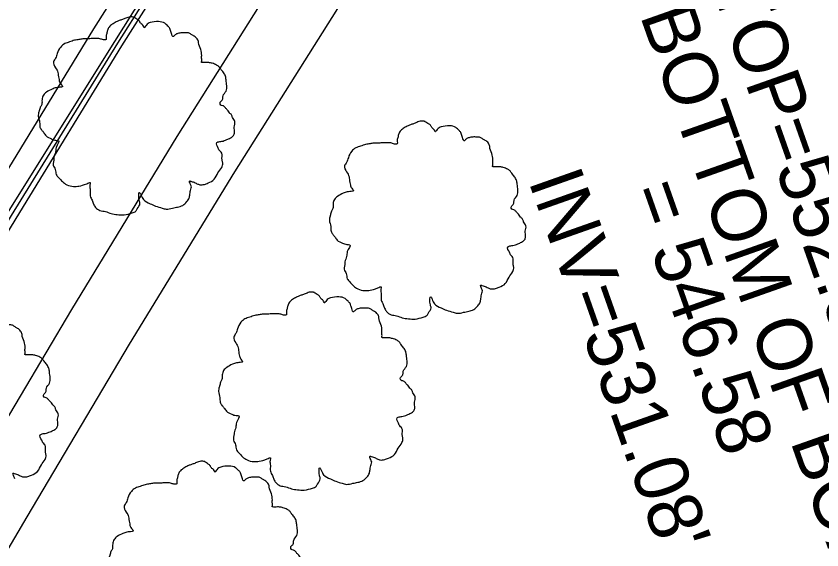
# Model space of a CAD drawing. Extents: x 2004847 to 2009016, y 1134161 to 1140101.
# Drawn here: x 2007935.1 to 2007994.5, y 1139061.5 to 1139100.8 of the extents above; entities that cross this region are included whole.
import ezdxf

# ---------------------------------------------------------------- set-up
doc = ezdxf.new("R2010")
doc.units = 0
for name, color, linetype in [('RD_EX_Conc', 7, 'Continuous'), ('RD_EX_Curb', 7, 'Continuous'), ('RD_EX_DR_Inlet_txCode', 7, 'Continuous'), ('RD_EX_Road', 7, 'Continuous'), ('RD_EX_VEG', 7, 'Continuous')]:
    doc.layers.add(name, color=color, linetype=linetype)

msp = doc.modelspace()

# ---------------------------------------------------------------- linework, layer by layer
at = {"layer": 'RD_EX_Conc'}
for points in [[(2008012.258, 1139192.316), (2008003.651, 1139179.799), (2007995.336, 1139167.43), (2007987.157, 1139154.821), (2007979.201, 1139142.322), (2007971.095, 1139129.729), (2007962.904, 1139117.197), (2007954.856, 1139104.534), (2007946.938, 1139091.958), (2007939.166, 1139079.213), (2007931.58, 1139066.441), (2007923.915, 1139053.39), (2007916.339, 1139040.676), (2007908.934, 1139027.568), (2007901.347, 1139014.745), (2007894.028, 1139001.836), (2007886.768, 1138988.672), (2007879.687, 1138975.615), (2007872.659, 1138962.368), (2007865.778, 1138949.249), (2007860.038, 1138937.972)], [(2008016.296, 1139189.467), (2008007.766, 1139177.029), (2007999.476, 1139164.697), (2007991.297, 1139152.062), (2007983.392, 1139139.642), (2007975.292, 1139127.057), (2007967.109, 1139114.537), (2007959.059, 1139101.871), (2007951.178, 1139089.355), (2007943.426, 1139076.643), (2007935.879, 1139063.936), (2007928.171, 1139050.827), (2007920.647, 1139038.202), (2007913.233, 1139025.065), (2007905.673, 1139012.288), (2007898.395, 1138999.453), (2007891.121, 1138986.277), (2007884.076, 1138973.288), (2007877.05, 1138960.043), (2007870.213, 1138947.011), (2007864.473, 1138935.734)]]:
    msp.add_lwpolyline(points, dxfattribs=at)
at = {"layer": 'RD_EX_Curb'}
for points in [[(2007989.294, 1139171.584), (2007981.119, 1139159.117), (2007979.485, 1139156.609), (2007974.548, 1139148.778), (2007966.518, 1139136.415), (2007958.375, 1139123.821), (2007950.518, 1139111.44), (2007942.559, 1139098.831), (2007934.71, 1139086.14), (2007927.171, 1139073.615), (2007919.542, 1139060.701), (2007912.08, 1139047.949), (2007907.108, 1139039.406), (2007903.841, 1139033.792), (2007897.425, 1139022.77), (2007893.765, 1139016.325), (2007888.06, 1139006.217), (2007880.903, 1138993.098), (2007873.794, 1138980.156), (2007868.217, 1138969.601), (2007863.906, 1138961.461), (2007859.666, 1138953.372), (2007853.475, 1138941.292)], [(2007989.587, 1139171.391), (2007981.43, 1139158.913), (2007979.864, 1139156.364), (2007974.922, 1139148.536), (2007966.859, 1139136.199), (2007958.73, 1139123.596), (2007950.844, 1139111.24), (2007942.864, 1139098.646), (2007935.074, 1139085.921), (2007927.484, 1139073.434), (2007919.887, 1139060.501), (2007912.354, 1139047.794), (2007907.427, 1139039.225), (2007904.224, 1139033.576), (2007897.811, 1139022.558), (2007894.152, 1139016.114), (2007888.449, 1139006.01), (2007881.293, 1138992.892), (2007874.167, 1138979.964), (2007868.571, 1138969.419), (2007864.285, 1138961.268), (2007860.13, 1138953.14), (2007853.85, 1138941.104)], [(2007974.293, 1139148.944), (2007973.079, 1139147.086), (2007966.226, 1139136.6), (2007958.109, 1139123.989), (2007950.254, 1139111.602), (2007942.331, 1139098.97), (2007934.431, 1139086.308), (2007926.899, 1139073.773), (2007919.27, 1139060.859), (2007911.797, 1139048.109), (2007906.875, 1139039.537), (2007903.644, 1139033.903)]]:
    msp.add_lwpolyline(points, dxfattribs=at)
at = {"layer": 'RD_EX_Road'}
msp.add_lwpolyline([(2007987.563, 1139172.722), (2007979.344, 1139160.275), (2007977.681, 1139157.78), (2007972.648, 1139150.012), (2007964.693, 1139137.571), (2007956.638, 1139124.92), (2007948.783, 1139112.504), (2007940.798, 1139099.901), (2007932.989, 1139087.177), (2007925.419, 1139074.63), (2007917.868, 1139061.671), (2007910.231, 1139048.995), (2007905.309, 1139040.422), (2007902.074, 1139034.791), (2007895.646, 1139023.748), (2007891.982, 1139017.295), (2007886.268, 1139007.171), (2007879.109, 1138994.048), (2007871.98, 1138981.089), (2007866.389, 1138970.541), (2007862.074, 1138962.393), (2007857.734, 1138954.34), (2007851.618, 1138942.222)], dxfattribs=at)
at = {"layer": 'RD_EX_VEG'}
for points in [[(2007943.793, 1139100.752), (2007943.493, 1139100.777), (2007943.168, 1139100.677), (2007942.918, 1139100.578), (2007942.693, 1139100.503), (2007942.468, 1139100.403), (2007942.168, 1139100.228), (2007941.943, 1139100.028), (2007941.818, 1139099.778), (2007941.768, 1139099.553), (2007941.718, 1139099.278), (2007941.718, 1139099.103), (2007941.594, 1139099.078), (2007941.444, 1139099.103), (2007941.194, 1139099.178), (2007940.944, 1139099.178), (2007940.694, 1139099.178), (2007940.344, 1139099.153), (2007939.994, 1139099.153), (2007939.719, 1139099.103), (2007939.394, 1139099.053), (2007939.02, 1139098.928), (2007938.67, 1139098.803), (2007938.37, 1139098.553), (2007938.12, 1139098.079), (2007937.995, 1139097.729), (2007937.845, 1139097.479), (2007937.995, 1139097.029), (2007938.17, 1139096.679), (2007938.195, 1139096.479), (2007938.27, 1139096.055), (2007938.37, 1139095.83), (2007938.495, 1139095.63), (2007938.42, 1139095.605), (2007938.045, 1139095.555), (2007937.745, 1139095.455), (2007937.32, 1139095.23), (2007937.095, 1139095.005), (2007936.995, 1139094.68), (2007936.971, 1139094.33), (2007936.871, 1139094.13), (2007936.796, 1139093.855), (2007936.771, 1139093.78), (2007936.721, 1139093.456), (2007936.821, 1139093.006), (2007936.846, 1139092.656), (2007936.971, 1139092.431), (2007937.12, 1139092.256), (2007937.295, 1139092.006), (2007937.695, 1139091.781), (2007938.02, 1139091.681), (2007938.22, 1139091.656), (2007938.045, 1139091.157), (2007937.995, 1139090.807), (2007937.87, 1139090.407), (2007937.87, 1139090.332), (2007937.82, 1139089.857), (2007937.97, 1139089.532), (2007938.045, 1139089.158), (2007938.22, 1139088.933), (2007938.495, 1139088.633), (2007938.82, 1139088.408), (2007939.32, 1139088.283), (2007939.719, 1139088.308), (2007940.294, 1139088.483), (2007940.544, 1139088.558), (2007940.519, 1139088.383), (2007940.544, 1139088.008), (2007940.544, 1139087.583), (2007940.694, 1139087.258), (2007940.794, 1139086.983), (2007940.944, 1139086.734), (2007941.269, 1139086.509), (2007941.668, 1139086.434), (2007942.093, 1139086.284), (2007942.543, 1139086.209), (2007943.043, 1139086.184), (2007943.643, 1139086.334), (2007943.917, 1139086.459), (2007944.017, 1139086.634), (2007944.217, 1139087.008), (2007944.167, 1139087.233), (2007944.192, 1139087.833), (2007944.292, 1139087.658), (2007944.467, 1139087.308), (2007944.967, 1139087.008), (2007945.367, 1139086.834), (2007945.842, 1139086.684), (2007946.142, 1139086.609), (2007946.616, 1139086.684), (2007946.991, 1139086.759), (2007947.366, 1139086.884), (2007947.666, 1139087.158), (2007947.841, 1139087.433), (2007947.891, 1139087.708), (2007947.966, 1139088.083), (2007948.016, 1139088.258)], [(2007948.016, 1139088.258), (2007947.941, 1139088.433), (2007947.891, 1139088.683), (2007947.966, 1139088.658), (2007948.141, 1139088.608), (2007948.416, 1139088.483), (2007948.64, 1139088.408), (2007948.965, 1139088.433), (2007949.24, 1139088.533), (2007949.69, 1139088.808), (2007949.965, 1139089.282), (2007950.24, 1139089.682), (2007950.315, 1139090.007), (2007950.265, 1139090.232), (2007950.24, 1139090.732), (2007950.04, 1139090.982), (2007949.99, 1139091.107), (2007949.89, 1139091.506), (2007949.965, 1139091.556), (2007950.24, 1139091.606), (2007950.615, 1139091.731), (2007950.889, 1139091.856), (2007951.114, 1139092.031), (2007951.189, 1139092.256), (2007951.164, 1139092.656), (2007951.214, 1139093.056), (2007951.139, 1139093.206), (2007951.039, 1139093.356), (2007950.964, 1139093.556), (2007950.814, 1139093.705), (2007950.715, 1139093.855), (2007950.615, 1139093.955), (2007950.49, 1139094.105), (2007950.315, 1139094.23), (2007950.165, 1139094.28), (2007950.115, 1139094.43), (2007950.265, 1139094.63), (2007950.315, 1139094.73), (2007950.34, 1139094.955), (2007950.565, 1139095.305), (2007950.615, 1139095.705), (2007950.565, 1139096.129), (2007950.515, 1139096.404), (2007950.365, 1139096.679), (2007950.165, 1139096.929), (2007950.04, 1139097.104), (2007949.865, 1139097.229), (2007949.54, 1139097.354), (2007949.29, 1139097.404), (2007948.94, 1139097.404), (2007948.74, 1139097.454), (2007948.765, 1139097.504), (2007948.765, 1139097.654), (2007948.765, 1139097.929), (2007948.69, 1139098.378), (2007948.54, 1139098.878), (2007948.54, 1139098.903), (2007948.44, 1139099.153), (2007948.216, 1139099.353), (2007948.041, 1139099.453), (2007947.841, 1139099.578), (2007947.591, 1139099.603), (2007947.291, 1139099.603), (2007947.016, 1139099.553), (2007946.816, 1139099.453), (2007946.641, 1139099.328), (2007946.566, 1139099.478), (2007946.466, 1139099.778), (2007946.416, 1139099.928), (2007946.266, 1139100.103), (2007946.042, 1139100.303), (2007945.592, 1139100.428), (2007944.967, 1139100.353), (2007944.667, 1139100.153), (2007944.517, 1139099.978), (2007944.467, 1139100.103), (2007944.267, 1139100.303), (2007944.167, 1139100.478), (2007943.992, 1139100.603), (2007943.843, 1139100.702), (2007943.743, 1139100.752)], [(2007965.248, 1139093.071), (2007964.948, 1139093.096), (2007964.623, 1139092.996), (2007964.373, 1139092.896), (2007964.148, 1139092.821), (2007963.923, 1139092.721), (2007963.623, 1139092.546), (2007963.398, 1139092.346), (2007963.273, 1139092.097), (2007963.223, 1139091.872), (2007963.173, 1139091.597), (2007963.173, 1139091.422), (2007963.049, 1139091.397), (2007962.899, 1139091.422), (2007962.649, 1139091.497), (2007962.399, 1139091.497), (2007962.149, 1139091.497), (2007961.799, 1139091.472), (2007961.449, 1139091.472), (2007961.174, 1139091.422), (2007960.849, 1139091.372), (2007960.475, 1139091.247), (2007960.125, 1139091.122), (2007959.825, 1139090.872), (2007959.575, 1139090.397), (2007959.45, 1139090.047), (2007959.3, 1139089.798), (2007959.45, 1139089.348), (2007959.625, 1139088.998), (2007959.65, 1139088.798), (2007959.725, 1139088.373), (2007959.825, 1139088.148), (2007959.95, 1139087.948), (2007959.875, 1139087.923), (2007959.5, 1139087.873), (2007959.2, 1139087.773), (2007958.775, 1139087.549), (2007958.55, 1139087.324), (2007958.45, 1139086.999), (2007958.426, 1139086.649), (2007958.326, 1139086.449), (2007958.251, 1139086.174), (2007958.226, 1139086.099), (2007958.176, 1139085.774), (2007958.276, 1139085.324), (2007958.301, 1139084.975), (2007958.426, 1139084.75), (2007958.575, 1139084.575), (2007958.75, 1139084.325), (2007959.15, 1139084.1), (2007959.475, 1139084), (2007959.675, 1139083.975), (2007959.5, 1139083.475), (2007959.45, 1139083.125), (2007959.325, 1139082.726), (2007959.325, 1139082.651), (2007959.275, 1139082.176), (2007959.425, 1139081.851), (2007959.5, 1139081.476), (2007959.675, 1139081.251), (2007959.95, 1139080.951), (2007960.275, 1139080.727), (2007960.775, 1139080.602), (2007961.174, 1139080.627), (2007961.749, 1139080.801), (2007961.999, 1139080.876), (2007961.974, 1139080.702), (2007961.999, 1139080.327), (2007961.999, 1139079.902), (2007962.149, 1139079.577), (2007962.249, 1139079.302), (2007962.399, 1139079.052), (2007962.724, 1139078.827), (2007963.123, 1139078.752), (2007963.548, 1139078.602), (2007963.998, 1139078.527), (2007964.498, 1139078.502), (2007965.098, 1139078.652), (2007965.372, 1139078.777), (2007965.472, 1139078.952), (2007965.672, 1139079.327), (2007965.622, 1139079.552), (2007965.647, 1139080.152), (2007965.747, 1139079.977), (2007965.922, 1139079.627), (2007966.422, 1139079.327), (2007966.822, 1139079.152), (2007967.297, 1139079.002), (2007967.597, 1139078.927), (2007968.071, 1139079.002), (2007968.446, 1139079.077), (2007968.821, 1139079.202), (2007969.121, 1139079.477), (2007969.296, 1139079.752), (2007969.346, 1139080.027), (2007969.421, 1139080.402), (2007969.471, 1139080.577)], [(2007969.471, 1139080.577), (2007969.396, 1139080.752), (2007969.346, 1139081.001), (2007969.421, 1139080.976), (2007969.596, 1139080.926), (2007969.871, 1139080.801), (2007970.095, 1139080.727), (2007970.42, 1139080.752), (2007970.695, 1139080.851), (2007971.145, 1139081.126), (2007971.42, 1139081.601), (2007971.695, 1139082.001), (2007971.77, 1139082.326), (2007971.72, 1139082.551), (2007971.695, 1139083.05), (2007971.495, 1139083.3), (2007971.445, 1139083.425), (2007971.345, 1139083.825), (2007971.42, 1139083.875), (2007971.695, 1139083.925), (2007972.07, 1139084.05), (2007972.344, 1139084.175), (2007972.569, 1139084.35), (2007972.644, 1139084.575), (2007972.619, 1139084.975), (2007972.669, 1139085.374), (2007972.594, 1139085.524), (2007972.494, 1139085.674), (2007972.419, 1139085.874), (2007972.269, 1139086.024), (2007972.17, 1139086.174), (2007972.07, 1139086.274), (2007971.945, 1139086.424), (2007971.77, 1139086.549), (2007971.62, 1139086.599), (2007971.57, 1139086.749), (2007971.72, 1139086.949), (2007971.77, 1139087.049), (2007971.795, 1139087.274), (2007972.02, 1139087.623), (2007972.07, 1139088.023), (2007972.02, 1139088.448), (2007971.97, 1139088.723), (2007971.82, 1139088.998), (2007971.62, 1139089.248), (2007971.495, 1139089.423), (2007971.32, 1139089.548), (2007970.995, 1139089.673), (2007970.745, 1139089.723), (2007970.395, 1139089.723), (2007970.195, 1139089.773), (2007970.22, 1139089.823), (2007970.22, 1139089.972), (2007970.22, 1139090.247), (2007970.145, 1139090.697), (2007969.995, 1139091.197), (2007969.995, 1139091.222), (2007969.895, 1139091.472), (2007969.671, 1139091.672), (2007969.496, 1139091.772), (2007969.296, 1139091.897), (2007969.046, 1139091.922), (2007968.746, 1139091.922), (2007968.471, 1139091.872), (2007968.271, 1139091.772), (2007968.096, 1139091.647), (2007968.021, 1139091.797), (2007967.921, 1139092.097), (2007967.871, 1139092.246), (2007967.721, 1139092.421), (2007967.497, 1139092.621), (2007967.047, 1139092.746), (2007966.422, 1139092.671), (2007966.122, 1139092.471), (2007965.972, 1139092.296), (2007965.922, 1139092.421), (2007965.722, 1139092.621), (2007965.622, 1139092.796), (2007965.447, 1139092.921), (2007965.298, 1139093.021), (2007965.198, 1139093.071)], [(2007957.08, 1139080.466), (2007956.78, 1139080.491), (2007956.455, 1139080.391), (2007956.205, 1139080.291), (2007955.98, 1139080.216), (2007955.756, 1139080.116), (2007955.456, 1139079.941), (2007955.231, 1139079.741), (2007955.106, 1139079.491), (2007955.056, 1139079.266), (2007955.006, 1139078.991), (2007955.006, 1139078.816), (2007954.881, 1139078.791), (2007954.731, 1139078.816), (2007954.481, 1139078.891), (2007954.231, 1139078.891), (2007953.981, 1139078.891), (2007953.631, 1139078.866), (2007953.282, 1139078.866), (2007953.007, 1139078.816), (2007952.682, 1139078.766), (2007952.307, 1139078.641), (2007951.957, 1139078.516), (2007951.657, 1139078.266), (2007951.407, 1139077.792), (2007951.282, 1139077.442), (2007951.133, 1139077.192), (2007951.282, 1139076.742), (2007951.457, 1139076.392), (2007951.482, 1139076.192), (2007951.557, 1139075.768), (2007951.657, 1139075.543), (2007951.782, 1139075.343), (2007951.707, 1139075.318), (2007951.332, 1139075.268), (2007951.033, 1139075.168), (2007950.608, 1139074.943), (2007950.383, 1139074.718), (2007950.283, 1139074.393), (2007950.258, 1139074.043), (2007950.158, 1139073.843), (2007950.083, 1139073.569), (2007950.058, 1139073.494), (2007950.008, 1139073.169), (2007950.108, 1139072.719), (2007950.133, 1139072.369), (2007950.258, 1139072.144), (2007950.408, 1139071.969), (2007950.583, 1139071.719), (2007950.983, 1139071.494), (2007951.307, 1139071.394), (2007951.507, 1139071.37), (2007951.332, 1139070.87), (2007951.282, 1139070.52), (2007951.158, 1139070.12), (2007951.158, 1139070.045), (2007951.108, 1139069.57), (2007951.257, 1139069.245), (2007951.332, 1139068.871), (2007951.507, 1139068.646), (2007951.782, 1139068.346), (2007952.107, 1139068.121), (2007952.607, 1139067.996), (2007953.007, 1139068.021), (2007953.582, 1139068.196), (2007953.831, 1139068.271), (2007953.806, 1139068.096), (2007953.831, 1139067.721), (2007953.831, 1139067.296), (2007953.981, 1139066.971), (2007954.081, 1139066.697), (2007954.231, 1139066.447), (2007954.556, 1139066.222), (2007954.956, 1139066.147), (2007955.381, 1139065.997), (2007955.831, 1139065.922), (2007956.33, 1139065.897), (2007956.93, 1139066.047), (2007957.205, 1139066.172), (2007957.305, 1139066.347), (2007957.505, 1139066.722), (2007957.455, 1139066.946), (2007957.48, 1139067.546), (2007957.58, 1139067.371), (2007957.755, 1139067.021), (2007958.254, 1139066.722), (2007958.654, 1139066.547), (2007959.129, 1139066.397), (2007959.429, 1139066.322), (2007959.904, 1139066.397), (2007960.279, 1139066.472), (2007960.653, 1139066.597), (2007960.953, 1139066.871), (2007961.128, 1139067.146), (2007961.178, 1139067.421), (2007961.253, 1139067.796), (2007961.303, 1139067.971)], [(2007961.303, 1139067.971), (2007961.228, 1139068.146), (2007961.178, 1139068.396), (2007961.253, 1139068.371), (2007961.428, 1139068.321), (2007961.703, 1139068.196), (2007961.928, 1139068.121), (2007962.253, 1139068.146), (2007962.528, 1139068.246), (2007962.977, 1139068.521), (2007963.252, 1139068.996), (2007963.527, 1139069.395), (2007963.602, 1139069.72), (2007963.552, 1139069.945), (2007963.527, 1139070.445), (2007963.327, 1139070.695), (2007963.277, 1139070.82), (2007963.177, 1139071.22), (2007963.252, 1139071.27), (2007963.527, 1139071.32), (2007963.902, 1139071.444), (2007964.177, 1139071.569), (2007964.402, 1139071.744), (2007964.477, 1139071.969), (2007964.452, 1139072.369), (2007964.502, 1139072.769), (2007964.427, 1139072.919), (2007964.327, 1139073.069), (2007964.252, 1139073.269), (2007964.102, 1139073.419), (2007964.002, 1139073.569), (2007963.902, 1139073.668), (2007963.777, 1139073.818), (2007963.602, 1139073.943), (2007963.452, 1139073.993), (2007963.402, 1139074.143), (2007963.552, 1139074.343), (2007963.602, 1139074.443), (2007963.627, 1139074.668), (2007963.852, 1139075.018), (2007963.902, 1139075.418), (2007963.852, 1139075.843), (2007963.802, 1139076.117), (2007963.652, 1139076.392), (2007963.452, 1139076.642), (2007963.327, 1139076.817), (2007963.152, 1139076.942), (2007962.827, 1139077.067), (2007962.578, 1139077.117), (2007962.228, 1139077.117), (2007962.028, 1139077.167), (2007962.053, 1139077.217), (2007962.053, 1139077.367), (2007962.053, 1139077.642), (2007961.978, 1139078.092), (2007961.828, 1139078.591), (2007961.828, 1139078.616), (2007961.728, 1139078.866), (2007961.503, 1139079.066), (2007961.328, 1139079.166), (2007961.128, 1139079.291), (2007960.878, 1139079.316), (2007960.578, 1139079.316), (2007960.304, 1139079.266), (2007960.104, 1139079.166), (2007959.929, 1139079.041), (2007959.854, 1139079.191), (2007959.754, 1139079.491), (2007959.704, 1139079.641), (2007959.554, 1139079.816), (2007959.329, 1139080.016), (2007958.879, 1139080.141), (2007958.254, 1139080.066), (2007957.955, 1139079.866), (2007957.805, 1139079.691), (2007957.755, 1139079.816), (2007957.555, 1139080.016), (2007957.455, 1139080.191), (2007957.28, 1139080.316), (2007957.13, 1139080.416), (2007957.03, 1139080.466)], [(2007934.996, 1139066.725), (2007934.921, 1139066.9), (2007934.871, 1139067.15), (2007934.946, 1139067.125), (2007935.12, 1139067.075), (2007935.395, 1139066.95), (2007935.62, 1139066.875), (2007935.945, 1139066.9), (2007936.22, 1139067), (2007936.67, 1139067.275), (2007936.945, 1139067.75), (2007937.22, 1139068.149), (2007937.295, 1139068.474), (2007937.245, 1139068.699), (2007937.22, 1139069.199), (2007937.02, 1139069.449), (2007936.97, 1139069.574), (2007936.87, 1139069.974), (2007936.945, 1139070.024), (2007937.22, 1139070.074), (2007937.594, 1139070.199), (2007937.869, 1139070.323), (2007938.094, 1139070.498), (2007938.169, 1139070.723), (2007938.144, 1139071.123), (2007938.194, 1139071.523), (2007938.119, 1139071.673), (2007938.019, 1139071.823), (2007937.944, 1139072.023), (2007937.794, 1139072.173), (2007937.694, 1139072.323), (2007937.594, 1139072.423), (2007937.469, 1139072.573), (2007937.295, 1139072.697), (2007937.145, 1139072.747), (2007937.095, 1139072.897), (2007937.245, 1139073.097), (2007937.295, 1139073.197), (2007937.319, 1139073.422), (2007937.544, 1139073.772), (2007937.594, 1139074.172), (2007937.544, 1139074.597), (2007937.494, 1139074.872), (2007937.344, 1139075.146), (2007937.145, 1139075.396), (2007937.02, 1139075.571), (2007936.845, 1139075.696), (2007936.52, 1139075.821), (2007936.27, 1139075.871), (2007935.92, 1139075.871), (2007935.72, 1139075.921), (2007935.745, 1139075.971), (2007935.745, 1139076.121), (2007935.745, 1139076.396), (2007935.67, 1139076.846), (2007935.52, 1139077.345), (2007935.52, 1139077.37), (2007935.42, 1139077.62), (2007935.195, 1139077.82), (2007935.021, 1139077.92), (2007934.821, 1139078.045), (2007934.571, 1139078.07), (2007934.271, 1139078.07), (2007933.996, 1139078.02), (2007933.796, 1139077.92), (2007933.621, 1139077.795), (2007933.546, 1139077.945), (2007933.446, 1139078.245), (2007933.396, 1139078.395), (2007933.246, 1139078.57), (2007933.021, 1139078.77), (2007932.572, 1139078.895), (2007931.947, 1139078.82), (2007931.647, 1139078.62), (2007931.497, 1139078.445), (2007931.447, 1139078.57), (2007931.247, 1139078.77), (2007931.147, 1139078.945), (2007930.972, 1139079.07), (2007930.822, 1139079.17), (2007930.722, 1139079.22)], [(2007949.001, 1139067.997), (2007948.701, 1139068.022), (2007948.377, 1139067.922), (2007948.127, 1139067.822), (2007947.902, 1139067.747), (2007947.677, 1139067.647), (2007947.377, 1139067.472), (2007947.152, 1139067.272), (2007947.027, 1139067.023), (2007946.977, 1139066.798), (2007946.927, 1139066.523), (2007946.927, 1139066.348), (2007946.802, 1139066.323), (2007946.652, 1139066.348), (2007946.402, 1139066.423), (2007946.153, 1139066.423), (2007945.903, 1139066.423), (2007945.553, 1139066.398), (2007945.203, 1139066.398), (2007944.928, 1139066.348), (2007944.603, 1139066.298), (2007944.228, 1139066.173), (2007943.879, 1139066.048), (2007943.579, 1139065.798), (2007943.329, 1139065.323), (2007943.204, 1139064.974), (2007943.054, 1139064.724), (2007943.204, 1139064.274), (2007943.379, 1139063.924), (2007943.404, 1139063.724), (2007943.479, 1139063.299), (2007943.579, 1139063.074), (2007943.704, 1139062.874), (2007943.629, 1139062.849), (2007943.254, 1139062.799), (2007942.954, 1139062.7), (2007942.529, 1139062.475), (2007942.304, 1139062.25), (2007942.204, 1139061.925), (2007942.179, 1139061.575), (2007942.079, 1139061.375), (2007942.004, 1139061.1), (2007941.979, 1139061.025), (2007941.929, 1139060.7), (2007942.029, 1139060.251), (2007942.054, 1139059.901), (2007942.179, 1139059.676), (2007942.329, 1139059.501), (2007942.504, 1139059.251), (2007942.904, 1139059.026), (2007943.229, 1139058.926), (2007943.429, 1139058.901), (2007943.254, 1139058.401), (2007943.204, 1139058.052), (2007943.079, 1139057.652), (2007943.079, 1139057.577), (2007943.029, 1139057.102), (2007943.179, 1139056.777), (2007943.254, 1139056.402), (2007943.429, 1139056.177), (2007943.704, 1139055.877), (2007944.028, 1139055.653), (2007944.528, 1139055.528), (2007944.928, 1139055.553), (2007945.503, 1139055.728), (2007945.753, 1139055.803), (2007945.728, 1139055.628), (2007945.753, 1139055.253), (2007945.753, 1139054.828), (2007945.903, 1139054.503), (2007946.003, 1139054.228), (2007946.153, 1139053.978), (2007946.477, 1139053.753), (2007946.877, 1139053.678), (2007947.302, 1139053.529), (2007947.752, 1139053.454), (2007948.252, 1139053.429), (2007948.851, 1139053.578), (2007949.126, 1139053.703), (2007949.226, 1139053.878), (2007949.426, 1139054.253), (2007949.376, 1139054.478), (2007949.401, 1139055.078), (2007949.501, 1139054.903), (2007949.676, 1139054.553), (2007950.176, 1139054.253), (2007950.576, 1139054.078), (2007951.05, 1139053.928), (2007951.35, 1139053.853), (2007951.825, 1139053.928), (2007952.2, 1139054.003), (2007952.575, 1139054.128), (2007952.875, 1139054.403), (2007953.05, 1139054.678), (2007953.1, 1139054.953), (2007953.174, 1139055.328), (2007953.224, 1139055.503)], [(2007953.224, 1139055.503), (2007953.15, 1139055.678), (2007953.1, 1139055.927), (2007953.174, 1139055.902), (2007953.349, 1139055.852), (2007953.624, 1139055.728), (2007953.849, 1139055.653), (2007954.174, 1139055.678), (2007954.449, 1139055.778), (2007954.899, 1139056.052), (2007955.174, 1139056.527), (2007955.448, 1139056.927), (2007955.523, 1139057.252), (2007955.473, 1139057.477), (2007955.448, 1139057.977), (2007955.249, 1139058.226), (2007955.199, 1139058.351), (2007955.099, 1139058.751), (2007955.174, 1139058.801), (2007955.448, 1139058.851), (2007955.823, 1139058.976), (2007956.098, 1139059.101), (2007956.323, 1139059.276), (2007956.398, 1139059.501), (2007956.373, 1139059.901), (2007956.423, 1139060.301), (2007956.348, 1139060.451), (2007956.248, 1139060.6), (2007956.173, 1139060.8), (2007956.023, 1139060.95), (2007955.923, 1139061.1), (2007955.823, 1139061.2), (2007955.698, 1139061.35), (2007955.523, 1139061.475), (2007955.374, 1139061.525), (2007955.324, 1139061.675), (2007955.473, 1139061.875), (2007955.523, 1139061.975), (2007955.548, 1139062.2), (2007955.773, 1139062.55), (2007955.823, 1139062.949), (2007955.773, 1139063.374), (2007955.723, 1139063.649), (2007955.573, 1139063.924), (2007955.374, 1139064.174), (2007955.249, 1139064.349), (2007955.074, 1139064.474), (2007954.749, 1139064.599), (2007954.499, 1139064.649), (2007954.149, 1139064.649), (2007953.949, 1139064.699), (2007953.974, 1139064.749), (2007953.974, 1139064.899), (2007953.974, 1139065.173), (2007953.899, 1139065.623), (2007953.749, 1139066.123), (2007953.749, 1139066.148), (2007953.649, 1139066.398), (2007953.424, 1139066.598), (2007953.249, 1139066.698), (2007953.05, 1139066.823), (2007952.8, 1139066.848), (2007952.5, 1139066.848), (2007952.225, 1139066.798), (2007952.025, 1139066.698), (2007951.85, 1139066.573), (2007951.775, 1139066.723), (2007951.675, 1139067.023), (2007951.625, 1139067.173), (2007951.475, 1139067.347), (2007951.25, 1139067.547), (2007950.8, 1139067.672), (2007950.176, 1139067.597), (2007949.876, 1139067.397), (2007949.726, 1139067.223), (2007949.676, 1139067.347), (2007949.476, 1139067.547), (2007949.376, 1139067.722), (2007949.201, 1139067.847), (2007949.051, 1139067.947), (2007948.951, 1139067.997)]]:
    msp.add_spline(points, degree=3, dxfattribs=at)

# ---------------------------------------------------------------- texts
at = {"layer": 'RD_EX_DR_Inlet_txCode'}
for s, height, p in [("TOP=552.54'", 4.00001, (2007986.323, 1139102.976)), ('BOTTOM OF BOX', 4.00001, (2007981.047, 1139100.903)), ("INV=531.08'", 4.00001, (2007972.819, 1139088.716)), ('= 546.58', 4, (2007980.31, 1139087.95))]:
    msp.add_text(s, height=height, rotation=289.44941, dxfattribs=at).set_placement(p)

doc.saveas('drawing.dxf')
